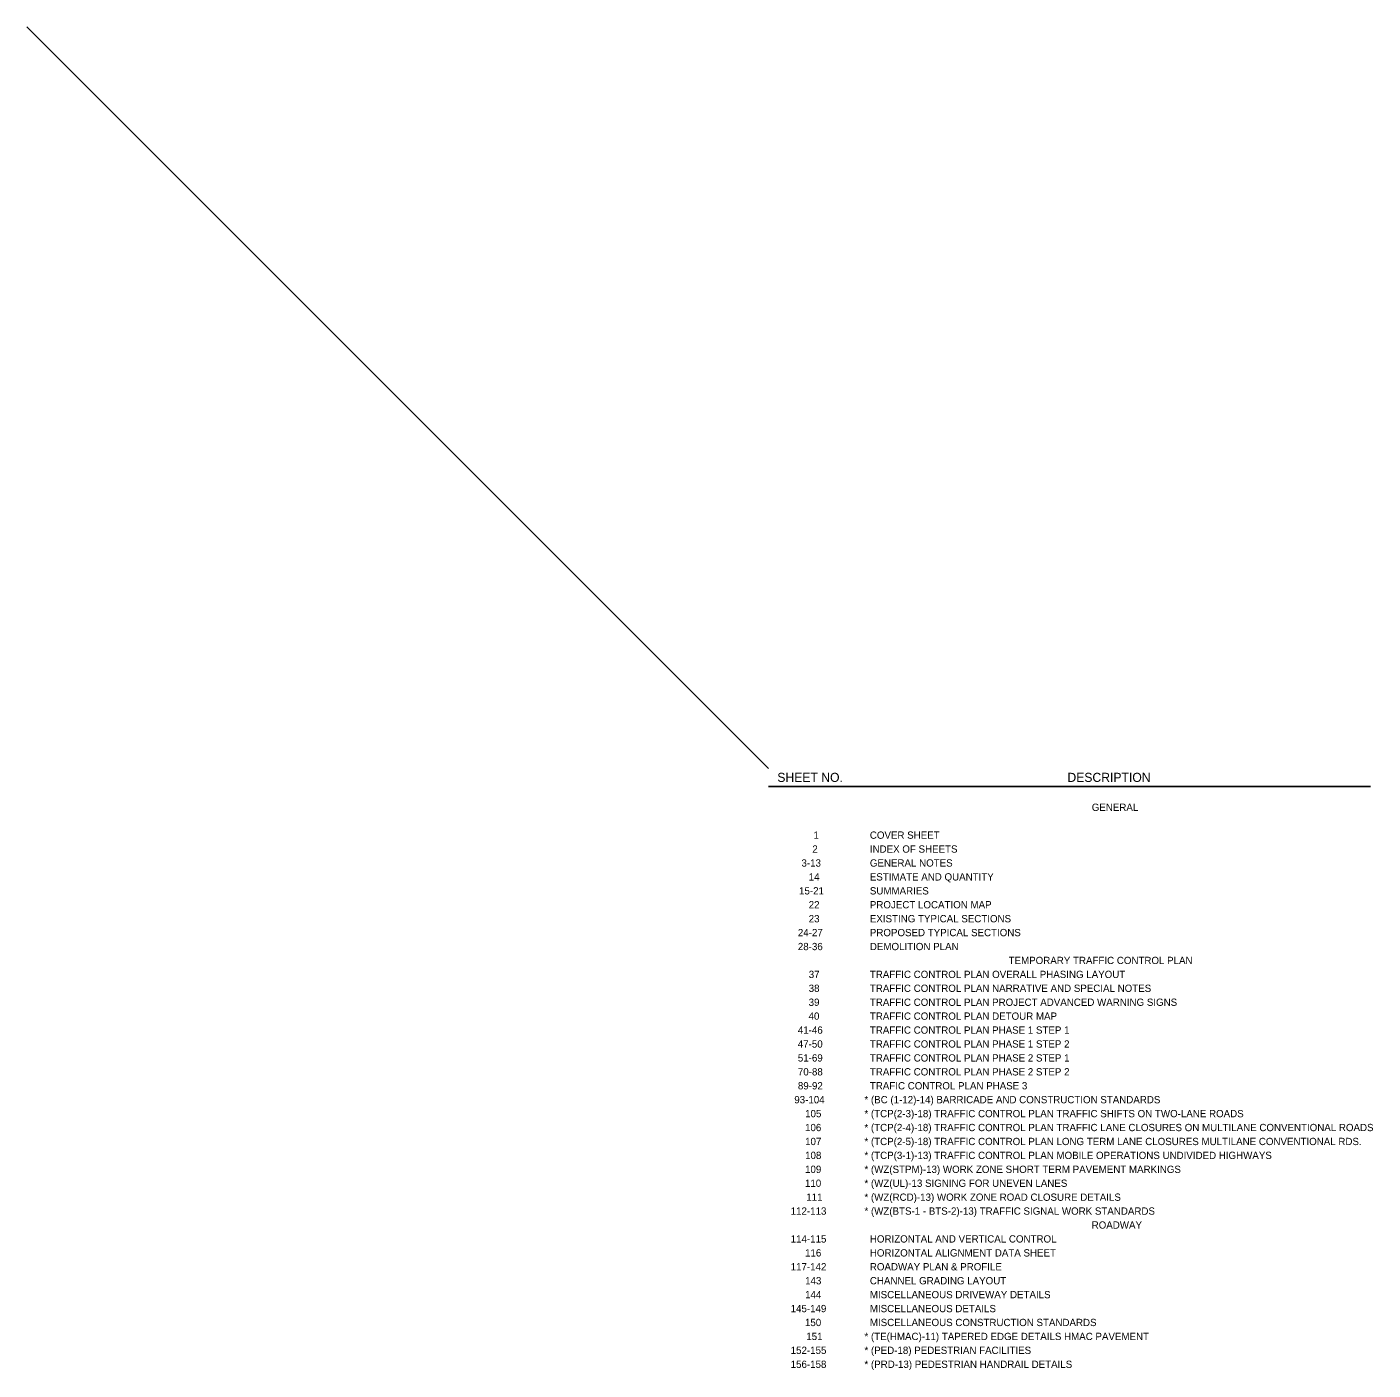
# Model space of a CAD drawing. Extents: x 2147351 to 2147573, y 2147143 to 2147587.
# Drawn here: x 2147351.1 to 2147573, y 2147365.3 to 2147586.6 of the extents above; entities that cross this region are included whole.
import ezdxf

# ---------------------------------------------------------------- set-up
doc = ezdxf.new("R2010")
doc.units = 0
for name, color, linetype in [('AXIOM TEXT', 7, 'Continuous'), ('Blank', 7, 'Continuous'), ('Default', 7, 'Continuous')]:
    doc.layers.add(name, color=color, linetype=linetype)

msp = doc.modelspace()

# ---------------------------------------------------------------- linework, layer by layer
at = {"layer": 'AXIOM TEXT'}
msp.add_line((2147473.35, 2147461.47), (2147572.57, 2147461.47), dxfattribs=at)
at = {"layer": 'Blank'}
msp.add_line((2147473.35, 2147464.44), (2147351.15, 2147586.65), dxfattribs=at)
at = {"layer": 'Default'}
msp.add_line((2147473.35, 2147464.44), (2147473.35, 2147464.44), dxfattribs=at)

# ---------------------------------------------------------------- texts
for s, height, p in [('SHEET NO.', 1.5, (2147474.82, 2147462.21)), ('DESCRIPTION', 1.5, (2147522.63, 2147462.21)), ('GENERAL', 1.2, (2147526.64, 2147457.43)), ('1', 1.2, (2147480.78, 2147452.84)), ('  COVER SHEET', 1.2, (2147489.18, 2147452.84)), ('2', 1.2, (2147480.59, 2147450.55)), ('  INDEX OF SHEETS', 1.2, (2147489.18, 2147450.55)), ('3-13', 1.2, (2147478.8, 2147448.25)), ('  GENERAL NOTES', 1.2, (2147489.18, 2147448.25)), ('14', 1.2, (2147480, 2147445.96)), ('  ESTIMATE AND QUANTITY', 1.2, (2147489.18, 2147445.96)), ('15-21', 1.2, (2147478.4, 2147443.66)), ('  SUMMARIES', 1.2, (2147489.18, 2147443.66)), ('22', 1.2, (2147479.99, 2147441.37)), ('  PROJECT LOCATION MAP', 1.2, (2147489.18, 2147441.37)), ('23', 1.2, (2147479.99, 2147439.07)), ('  EXISTING TYPICAL SECTIONS', 1.2, (2147489.18, 2147439.07)), ('24-27', 1.2, (2147478.21, 2147436.78)), ('  PROPOSED TYPICAL SECTIONS', 1.2, (2147489.18, 2147436.78)), ('28-36', 1.2, (2147478.2, 2147434.48)), ('  DEMOLITION PLAN', 1.2, (2147489.18, 2147434.48)), ('TEMPORARY TRAFFIC CONTROL PLAN', 1.2, (2147512.94, 2147432.19)), ('37', 1.2, (2147480, 2147429.89)), ('  TRAFFIC CONTROL PLAN OVERALL PHASING LAYOUT', 1.2, (2147489.18, 2147429.89)), ('38', 1.2, (2147479.99, 2147427.6)), ('  TRAFFIC CONTROL PLAN NARRATIVE AND SPECIAL NOTES', 1.2, (2147489.18, 2147427.6)), ('39', 1.2, (2147479.98, 2147425.3)), ('  TRAFFIC CONTROL PLAN PROJECT ADVANCED WARNING SIGNS', 1.2, (2147489.18, 2147425.3)), ('40', 1.2, (2147479.97, 2147423.01)), ('  TRAFFIC CONTROL PLAN DETOUR MAP', 1.2, (2147489.18, 2147423.01)), ('41-46', 1.2, (2147478.2, 2147420.71)), ('  TRAFFIC CONTROL PLAN PHASE 1 STEP 1', 1.2, (2147489.18, 2147420.71)), ('47-50', 1.2, (2147478.19, 2147418.42)), ('  TRAFFIC CONTROL PLAN PHASE 1 STEP 2', 1.2, (2147489.18, 2147418.42)), ('51-69', 1.2, (2147478.2, 2147416.12)), ('  TRAFFIC CONTROL PLAN PHASE 2 STEP 1', 1.2, (2147489.18, 2147416.12)), ('70-88', 1.2, (2147478.21, 2147413.83)), ('  TRAFFIC CONTROL PLAN PHASE 2 STEP 2', 1.2, (2147489.18, 2147413.83)), ('89-92', 1.2, (2147478.21, 2147411.53)), ('  TRAFIC CONTROL PLAN PHASE 3', 1.2, (2147489.18, 2147411.53)), ('93-104', 1.2, (2147477.62, 2147409.24)), ('* (BC (1-12)-14) BARRICADE AND CONSTRUCTION STANDARDS', 1.2, (2147489.18, 2147409.24)), ('105', 1.2, (2147479.4, 2147406.94)), ('* (TCP(2-3)-18) TRAFFIC CONTROL PLAN TRAFFIC SHIFTS ON TWO-LANE ROADS', 1.2, (2147489.18, 2147406.94)), ('106', 1.2, (2147479.39, 2147404.65)), ('* (TCP(2-4)-18) TRAFFIC CONTROL PLAN TRAFFIC LANE CLOSURES ON MULTILANE CONVENTIONAL ROADS', 1.2, (2147489.18, 2147404.65)), ('107', 1.2, (2147479.4, 2147402.35)), ('* (TCP(2-5)-18) TRAFFIC CONTROL PLAN LONG TERM LANE CLOSURES MULTILANE CONVENTIONAL RDS.', 1.2, (2147489.18, 2147402.35)), ('108', 1.2, (2147479.4, 2147400.06)), ('* (TCP(3-1)-13) TRAFFIC CONTROL PLAN MOBILE OPERATIONS UNDIVIDED HIGHWAYS', 1.2, (2147489.18, 2147400.06)), ('109', 1.2, (2147479.39, 2147397.76)), ('* (WZ(STPM)-13) WORK ZONE SHORT TERM PAVEMENT MARKINGS', 1.2, (2147489.18, 2147397.76)), ('110', 1.2, (2147479.38, 2147395.47)), ('* (WZ(UL)-13 SIGNING FOR UNEVEN LANES', 1.2, (2147489.18, 2147395.47)), ('111', 1.2, (2147479.59, 2147393.17)), ('* (WZ(RCD)-13) WORK ZONE ROAD CLOSURE DETAILS', 1.2, (2147489.18, 2147393.17)), ('112-113', 1.2, (2147477.02, 2147390.88)), ('* (WZ(BTS-1 - BTS-2)-13) TRAFFIC SIGNAL WORK STANDARDS', 1.2, (2147489.18, 2147390.88)), ('ROADWAY', 1.2, (2147526.63, 2147388.58)), ('114-115', 1.2, (2147477.02, 2147386.29)), ('  HORIZONTAL AND VERTICAL CONTROL', 1.2, (2147489.18, 2147386.29)), ('116', 1.2, (2147479.39, 2147383.99)), ('  HORIZONTAL ALIGNMENT DATA SHEET', 1.2, (2147489.18, 2147383.99)), ('117-142', 1.2, (2147477.02, 2147381.7)), ('  ROADWAY PLAN & PROFILE', 1.2, (2147489.18, 2147381.7)), ('143', 1.2, (2147479.4, 2147379.4)), ('  CHANNEL GRADING LAYOUT', 1.2, (2147489.18, 2147379.4)), ('144', 1.2, (2147479.4, 2147377.11)), ('  MISCELLANEOUS DRIVEWAY DETAILS', 1.2, (2147489.18, 2147377.11)), ('145-149', 1.2, (2147477.01, 2147374.81)), ('  MISCELLANEOUS DETAILS', 1.2, (2147489.18, 2147374.81)), ('150', 1.2, (2147479.38, 2147372.52)), ('  MISCELLANEOUS CONSTRUCTION STANDARDS', 1.2, (2147489.18, 2147372.52)), ('151', 1.2, (2147479.59, 2147370.22)), ('* (TE(HMAC)-11) TAPERED EDGE DETAILS HMAC PAVEMENT', 1.2, (2147489.18, 2147370.22)), ('152-155', 1.2, (2147477.02, 2147367.93)), ('* (PED-18) PEDESTRIAN FACILITIES', 1.2, (2147489.18, 2147367.93)), ('156-158', 1.2, (2147477.02, 2147365.63)), ('* (PRD-13) PEDESTRIAN HANDRAIL DETAILS', 1.2, (2147489.18, 2147365.63))]:
    msp.add_text(s, height=height, dxfattribs=at).set_placement(p)

doc.saveas('drawing.dxf')
